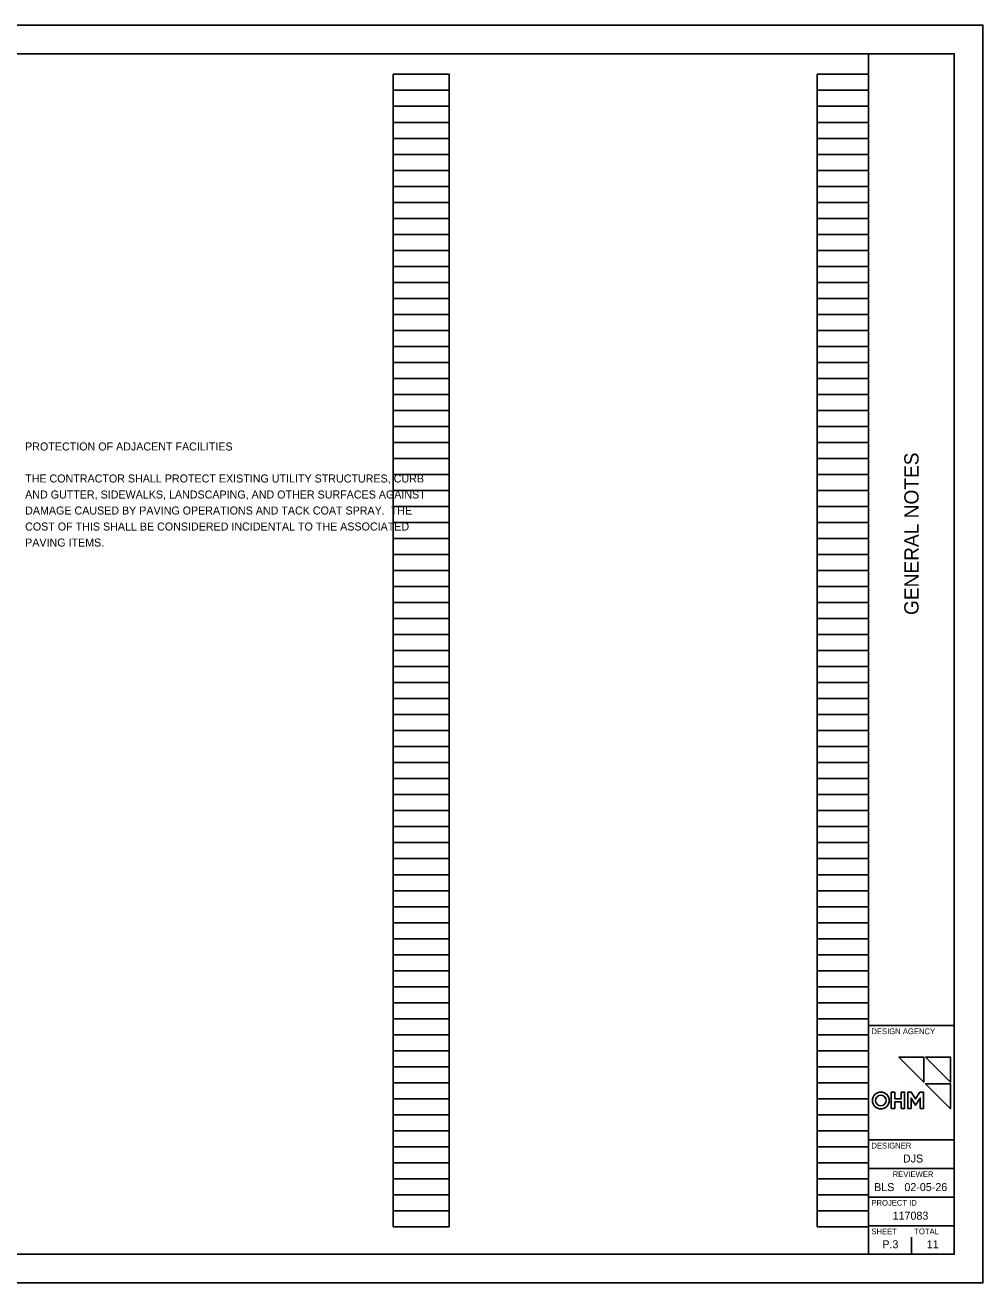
# Model space of a CAD drawing. Extents: x 0 to 34, y 0 to 22.
# Drawn here: x 17.24 to 34, y 0 to 22 of the extents above; entities that cross this region are included whole.
import ezdxf

# ---------------------------------------------------------------- set-up
doc = ezdxf.new("R2010")
doc.units = 0
for name, color, linetype in [('SH_Border', 7, 'Continuous'), ('SH_Cut_Line', 7, 'Continuous'), ('SH_Data', 7, 'Continuous'), ('SH_Text', 7, 'Continuous'), ('TX_P_Misc', 7, 'Continuous')]:
    doc.layers.add(name, color=color, linetype=linetype)

msp = doc.modelspace()

# ---------------------------------------------------------------- linework, layer by layer
at = {"layer": 'SH_Border'}
for p, q in [((32, 0.5), (32, 21.5)), ((32, 4.5), (33.5, 4.5)), ((32, 2.5), (33.5, 2.5)), ((32, 2), (33.5, 2)), ((32, 1.5), (33.5, 1.5)), ((32, 1), (33.5, 1))]:
    msp.add_line(p, q, dxfattribs=at)
msp.add_lwpolyline([(1.5, 21.5), (33.5, 21.5), (33.5, 0.5), (1.5, 0.5)], close=True, dxfattribs=at)
at = {"layer": 'SH_Cut_Line'}
msp.add_lwpolyline([(0, 0), (34, 0), (34, 22), (0, 22)], close=True, dxfattribs=at)
at = {"layer": 'SH_Data'}
for p, q in [((23.68, 0.98), (23.68, 21.14)), ((23.68, 21.14), (24.66, 21.14)), ((24.66, 0.98), (24.66, 21.14)), ((31.1, 0.98), (31.1, 21.14)), ((31.1, 21.14), (32, 21.14)), ((32, 0.98), (32, 21.14)), ((23.68, 20.86), (24.66, 20.86)), ((31.1, 20.86), (32, 20.86)), ((23.68, 20.58), (24.66, 20.58)), ((31.1, 20.58), (32, 20.58)), ((23.68, 20.3), (24.66, 20.3)), ((31.1, 20.3), (32, 20.3)), ((23.68, 20.02), (24.66, 20.02)), ((31.1, 20.02), (32, 20.02)), ((23.68, 19.74), (24.66, 19.74)), ((31.1, 19.74), (32, 19.74)), ((23.68, 19.46), (24.66, 19.46)), ((31.1, 19.46), (32, 19.46)), ((23.68, 19.18), (24.66, 19.18)), ((31.1, 19.18), (32, 19.18)), ((23.68, 18.9), (24.66, 18.9)), ((31.1, 18.9), (32, 18.9)), ((23.68, 18.62), (24.66, 18.62)), ((31.1, 18.62), (32, 18.62)), ((23.68, 18.34), (24.66, 18.34)), ((31.1, 18.34), (32, 18.34)), ((23.68, 18.06), (24.66, 18.06)), ((31.1, 18.06), (32, 18.06)), ((23.68, 17.78), (24.66, 17.78)), ((31.1, 17.78), (32, 17.78)), ((23.68, 17.5), (24.66, 17.5)), ((31.1, 17.5), (32, 17.5)), ((23.68, 17.22), (24.66, 17.22)), ((31.1, 17.22), (32, 17.22)), ((23.68, 16.94), (24.66, 16.94)), ((31.1, 16.94), (32, 16.94)), ((23.68, 16.66), (24.66, 16.66)), ((31.1, 16.66), (32, 16.66)), ((23.68, 16.38), (24.66, 16.38)), ((31.1, 16.38), (32, 16.38)), ((23.68, 16.1), (24.66, 16.1)), ((31.1, 16.1), (32, 16.1)), ((23.68, 15.82), (24.66, 15.82)), ((31.1, 15.82), (32, 15.82)), ((23.68, 15.54), (24.66, 15.54)), ((31.1, 15.54), (32, 15.54)), ((23.68, 15.26), (24.66, 15.26)), ((31.1, 15.26), (32, 15.26)), ((23.68, 14.98), (24.66, 14.98)), ((31.1, 14.98), (32, 14.98)), ((23.68, 14.7), (24.66, 14.7)), ((31.1, 14.7), (32, 14.7)), ((23.68, 14.42), (24.66, 14.42)), ((31.1, 14.42), (32, 14.42)), ((23.68, 14.14), (24.66, 14.14)), ((31.1, 14.14), (32, 14.14)), ((23.68, 13.86), (24.66, 13.86)), ((31.1, 13.86), (32, 13.86)), ((23.68, 13.58), (24.66, 13.58)), ((31.1, 13.58), (32, 13.58)), ((23.68, 13.3), (24.66, 13.3)), ((31.1, 13.3), (32, 13.3)), ((23.68, 13.02), (24.66, 13.02)), ((31.1, 13.02), (32, 13.02)), ((23.68, 12.74), (24.66, 12.74)), ((31.1, 12.74), (32, 12.74)), ((23.68, 12.46), (24.66, 12.46)), ((31.1, 12.46), (32, 12.46)), ((23.68, 12.18), (24.66, 12.18)), ((31.1, 12.18), (32, 12.18)), ((23.68, 11.9), (24.66, 11.9)), ((31.1, 11.9), (32, 11.9)), ((23.68, 11.62), (24.66, 11.62)), ((31.1, 11.62), (32, 11.62)), ((23.68, 11.34), (24.66, 11.34)), ((31.1, 11.34), (32, 11.34)), ((23.68, 11.06), (24.66, 11.06)), ((31.1, 11.06), (32, 11.06)), ((23.68, 10.78), (24.66, 10.78)), ((31.1, 10.78), (32, 10.78)), ((23.68, 10.5), (24.66, 10.5)), ((31.1, 10.5), (32, 10.5)), ((23.68, 10.22), (24.66, 10.22)), ((31.1, 10.22), (32, 10.22)), ((23.68, 9.94), (24.66, 9.94)), ((31.1, 9.94), (32, 9.94)), ((23.68, 9.66), (24.66, 9.66)), ((31.1, 9.66), (32, 9.66)), ((23.68, 9.38), (24.66, 9.38)), ((31.1, 9.38), (32, 9.38)), ((23.68, 9.1), (24.66, 9.1)), ((31.1, 9.1), (32, 9.1)), ((23.68, 8.82), (24.66, 8.82)), ((31.1, 8.82), (32, 8.82)), ((23.68, 8.54), (24.66, 8.54)), ((31.1, 8.54), (32, 8.54)), ((23.68, 8.26), (24.66, 8.26)), ((31.1, 8.26), (32, 8.26)), ((23.68, 7.98), (24.66, 7.98)), ((31.1, 7.98), (32, 7.98)), ((23.68, 7.7), (24.66, 7.7)), ((31.1, 7.7), (32, 7.7)), ((23.68, 7.42), (24.66, 7.42)), ((31.1, 7.42), (32, 7.42)), ((23.68, 7.14), (24.66, 7.14)), ((31.1, 7.14), (32, 7.14)), ((23.68, 6.86), (24.66, 6.86)), ((31.1, 6.86), (32, 6.86)), ((23.68, 6.58), (24.66, 6.58)), ((31.1, 6.58), (32, 6.58)), ((23.68, 6.3), (24.66, 6.3)), ((31.1, 6.3), (32, 6.3)), ((23.68, 6.02), (24.66, 6.02)), ((31.1, 6.02), (32, 6.02)), ((23.68, 5.74), (24.66, 5.74)), ((31.1, 5.74), (32, 5.74)), ((23.68, 5.46), (24.66, 5.46)), ((31.1, 5.46), (32, 5.46)), ((23.68, 5.18), (24.66, 5.18)), ((31.1, 5.18), (32, 5.18)), ((23.68, 4.9), (24.66, 4.9)), ((31.1, 4.9), (32, 4.9)), ((23.68, 4.62), (24.66, 4.62)), ((31.1, 4.62), (32, 4.62)), ((23.68, 4.34), (24.66, 4.34)), ((31.1, 4.34), (32, 4.34)), ((23.68, 4.06), (24.66, 4.06)), ((31.1, 4.06), (32, 4.06)), ((23.68, 3.78), (24.66, 3.78)), ((31.1, 3.78), (32, 3.78)), ((23.68, 3.5), (24.66, 3.5)), ((31.1, 3.5), (32, 3.5)), ((32.75, 3.5), (32.75, 3.5)), ((23.68, 3.22), (24.66, 3.22)), ((31.1, 3.22), (32, 3.22)), ((23.68, 2.94), (24.66, 2.94)), ((31.1, 2.94), (32, 2.94)), ((23.68, 2.66), (24.66, 2.66)), ((31.1, 2.66), (32, 2.66)), ((23.68, 2.38), (24.66, 2.38)), ((31.1, 2.38), (32, 2.38)), ((23.68, 2.1), (24.66, 2.1)), ((31.1, 2.1), (32, 2.1)), ((23.68, 1.82), (24.66, 1.82)), ((31.1, 1.82), (32, 1.82)), ((23.68, 1.54), (24.66, 1.54)), ((31.1, 1.54), (32, 1.54)), ((23.68, 1.26), (24.66, 1.26)), ((31.1, 1.26), (32, 1.26)), ((23.68, 0.98), (24.66, 0.98)), ((31.1, 0.98), (32, 0.98)), ((32.375, 0.675), (32.375, 0.675)), ((32.75, 0.5), (32.75, 0.8))]:
    msp.add_line(p, q, dxfattribs=at)
at = {"layer": 'SH_Text'}
for points in [[(32.966, 3.948), (32.966, 3.51), (32.53, 3.948)], [(33.433, 3.948), (33.433, 3.51), (32.997, 3.948)], [(32.397, 3.333), (32.457, 3.333), (32.457, 3.22), (32.571, 3.22), (32.571, 3.333), (32.631, 3.333), (32.631, 3.052), (32.571, 3.052), (32.571, 3.166), (32.457, 3.166), (32.457, 3.052), (32.397, 3.052)], [(32.9, 3.335), (32.963, 3.335), (32.963, 3.052), (32.903, 3.052), (32.903, 3.233), (32.824, 3.108), (32.745, 3.233), (32.745, 3.052), (32.685, 3.052), (32.685, 3.335), (32.748, 3.335), (32.824, 3.216)], [(33.433, 3.483), (33.433, 3.045), (32.997, 3.483)]]:
    msp.add_lwpolyline(points, close=True, dxfattribs=at)
at = {"layer": 'TX_P_Misc'}
for p, q in [((32.745, 3.052), (32.745, 3.233)), ((32.745, 3.233), (32.824, 3.108)), ((32.824, 3.108), (32.903, 3.233)), ((32.903, 3.233), (32.903, 3.052))]:
    msp.add_line(p, q, dxfattribs=at)
for points in [[(32.53, 3.948), (32.966, 3.51), (32.966, 3.948), (32.53, 3.948)], [(32.997, 3.948), (33.433, 3.51), (33.433, 3.948), (32.997, 3.948)], [(32.824, 3.216), (32.748, 3.335), (32.685, 3.335), (32.685, 3.052), (32.745, 3.052)], [(32.903, 3.052), (32.963, 3.052), (32.963, 3.335), (32.9, 3.335), (32.824, 3.216)], [(32.997, 3.483), (33.433, 3.045), (33.433, 3.483), (32.997, 3.483)]]:
    msp.add_lwpolyline(points, dxfattribs=at)
msp.add_lwpolyline([(32.397, 3.333), (32.457, 3.333), (32.457, 3.22), (32.571, 3.22), (32.571, 3.333), (32.631, 3.333), (32.631, 3.052), (32.571, 3.052), (32.571, 3.166), (32.457, 3.166), (32.457, 3.052), (32.397, 3.052)], close=True, dxfattribs=at)
for radius in [0.148, 0.148, 0.0927, 0.0927]:
    msp.add_circle((32.215, 3.19), radius, dxfattribs=at)

# ---------------------------------------------------------------- texts
at = {"layer": 'SH_Data'}
msp.add_text('GENERAL NOTES', height=0.25, rotation=90, dxfattribs=at).set_placement((32.875, 11.682))
for s, height, p in [('DESIGN AGENCY', 0.1, (32.05, 4.35)), ('DESIGNER', 0.1, (32.05, 2.35)), ('DJS', 0.14, (32.602, 2.105)), ('REVIEWER', 0.1, (32.422, 1.85)), ('BLS', 0.14, (32.097, 1.605)), ('02-05-26', 0.14, (32.627, 1.605)), ('PROJECT ID', 0.1, (32.05, 1.35)), ('117083', 0.14, (32.421, 1.105)), ('SHEET', 0.1, (32.05, 0.85)), ('TOTAL', 0.1, (32.8, 0.85)), ('P.3', 0.14, (32.241, 0.605)), ('11', 0.14, (33.019, 0.605))]:
    msp.add_text(s, height=height, dxfattribs=at).set_placement(p)
at = {"layer": 'SH_Text'}
for s, p in [('PROTECTION OF ADJACENT FACILITIES', (17.24, 14.56)), ('THE CONTRACTOR SHALL PROTECT EXISTING UTILITY STRUCTURES, CURB ', (17.24, 14)), ('AND GUTTER, SIDEWALKS, LANDSCAPING, AND OTHER SURFACES AGAINST', (17.24, 13.72)), ('DAMAGE CAUSED BY PAVING OPERATIONS AND TACK COAT SPRAY.  THE ', (17.24, 13.44)), ('COST OF THIS SHALL BE CONSIDERED INCIDENTAL TO THE ASSOCIATED ', (17.24, 13.16)), ('PAVING ITEMS.', (17.24, 12.88))]:
    msp.add_text(s, height=0.14, dxfattribs=at).set_placement(p)

doc.saveas('drawing.dxf')
